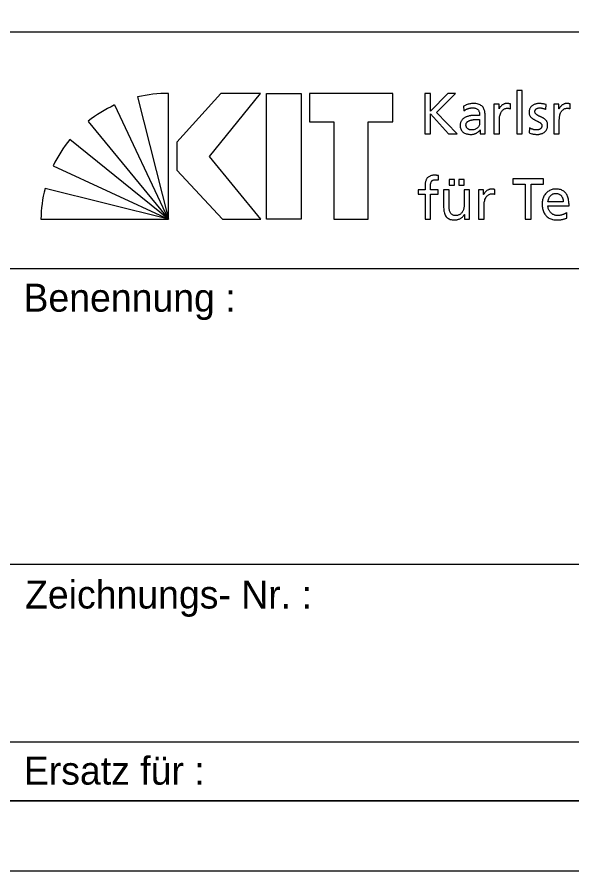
# Model space of a CAD drawing. Extents: x 0 to 119, y 0 to 84.
# Drawn here: x 101.13 to 109.07, y 0 to 12.21 of the extents above; entities that cross this region are included whole.
import ezdxf

# ---------------------------------------------------------------- set-up
doc = ezdxf.new("R2010")
doc.units = 0
doc.layers.add('90_Plankopf', color=7, linetype='Continuous')

msp = doc.modelspace()

# ---------------------------------------------------------------- linework, layer by layer
at = {"layer": '90_Plankopf'}
for p, q in [((82.224, 11.998), (117.8, 11.998)), ((82.224, 11.998), (117.8, 11.998)), ((103.296, 9.317), (103.296, 11.117)), ((106.962, 11.117), (106.962, 10.541)), ((102.855, 11.067), (103.296, 9.317)), ((103.296, 9.317), (102.527, 10.95)), ((107.516, 10.932), (107.52, 10.866)), ((108.185, 10.897), (108.185, 10.966)), ((108.691, 10.888), (108.698, 10.956)), ((109.042, 10.897), (109.042, 10.966)), ((107.824, 10.624), (107.824, 10.798)), ((102.149, 10.717), (103.296, 9.317)), ((107.746, 10.742), (107.746, 10.705)), ((108.459, 10.624), (108.455, 10.554)), ((106.962, 10.541), (107.044, 10.541)), ((107.301, 10.541), (107.422, 10.541)), ((103.296, 9.317), (101.887, 10.457)), ((101.648, 10.083), (103.296, 9.317)), ((107.155, 9.879), (107.158, 9.941)), ((103.296, 9.317), (101.532, 9.758)), ((107.965, 9.673), (107.965, 9.742)), ((108.941, 9.568), (108.723, 9.568)), ((108.723, 9.51), (109.024, 9.51)), ((108.992, 9.335), (108.992, 9.412)), ((101.473, 9.317), (103.296, 9.317)), ((101, 8.614), (117.8, 8.614)), ((101, 4.384), (117.8, 4.384)), ((101, 1.846), (117.8, 1.846)), ((117.8, 1), (82.224, 1)), ((84.56, 1), (117.8, 1)), ((84.56, 1), (117.8, 1))]:
    msp.add_line(p, q, dxfattribs=at)
for points in [[(0, 0), (118.8, 0), (118.8, 84), (0, 84)], [(5, 83), (117.8, 83), (117.8, 1), (5, 1)], [(104.613, 11.117), (104.047, 11.117), (103.415, 10.42), (103.415, 10.018), (104.068, 9.317), (104.617, 9.317), (103.884, 10.213)], [(105.194, 11.117), (105.194, 9.317), (104.7, 9.317), (104.7, 11.117)], [(105.312, 11.117), (105.312, 10.712), (105.66, 10.712), (105.66, 9.317), (106.154, 9.317), (106.154, 10.712), (106.502, 10.712), (106.502, 11.117)]]:
    msp.add_lwpolyline(points, close=True, dxfattribs=at)
for points in [[(107.422, 10.541), (107.129, 10.845), (107.4, 11.117), (107.29, 11.117), (107.044, 10.864), (107.044, 11.117), (106.962, 11.117)], [(108.276, 10.541), (108.354, 10.541), (108.354, 11.16), (108.276, 11.16), (108.276, 10.541)], [(108.024, 10.897), (108.023, 10.897), (108.023, 10.962), (107.95, 10.962), (107.95, 10.541), (108.028, 10.541), (108.028, 10.733)], [(108.881, 10.897), (108.88, 10.897), (108.88, 10.962), (108.807, 10.962), (108.807, 10.541), (108.885, 10.541), (108.885, 10.733)], [(107.044, 10.541), (107.044, 10.823), (107.301, 10.541)], [(107.753, 10.596), (107.754, 10.596), (107.754, 10.541), (107.827, 10.541)], [(108.398, 9.317), (108.481, 9.317), (108.481, 9.821), (108.66, 9.821), (108.66, 9.893), (108.219, 9.893), (108.219, 9.821), (108.398, 9.821), (108.398, 9.317)], [(106.965, 9.777), (106.965, 9.738), (106.866, 9.738), (106.866, 9.676), (106.965, 9.676), (106.965, 9.317), (107.042, 9.317), (107.042, 9.676), (107.154, 9.676), (107.154, 9.738), (107.042, 9.738), (107.042, 9.784)], [(107.311, 9.885), (107.311, 9.803), (107.388, 9.803), (107.388, 9.885), (107.311, 9.885)], [(107.446, 9.885), (107.446, 9.803), (107.524, 9.803), (107.524, 9.885), (107.446, 9.885)], [(107.308, 9.52), (107.308, 9.738), (107.231, 9.738), (107.231, 9.488)], [(107.603, 9.317), (107.603, 9.738), (107.525, 9.738), (107.525, 9.543)], [(107.804, 9.673), (107.803, 9.673), (107.803, 9.738), (107.73, 9.738), (107.73, 9.317), (107.808, 9.317), (107.808, 9.509)], [(107.526, 9.384), (107.528, 9.384), (107.528, 9.317), (107.603, 9.317)]]:
    msp.add_lwpolyline(points, dxfattribs=at)
for centre, start, end in [((103.29, 9.211), 89.8053, 103.1895), ((103.332, 9.224), 115.0126, 128.3968), ((103.363, 9.253), 140.7898, 154.174), ((103.378, 9.288), 165.7222, 179.1064)]:
    msp.add_arc(centre, 1.906, start, end, dxfattribs=at)
for points in [[(107.824, 10.798), (107.824, 10.836), (107.818, 10.868), (107.807, 10.894), (107.795, 10.92), (107.777, 10.939), (107.752, 10.952), (107.727, 10.965), (107.694, 10.972), (107.654, 10.972), (107.628, 10.972), (107.603, 10.968), (107.58, 10.961), (107.556, 10.954), (107.535, 10.944), (107.516, 10.932)], [(107.52, 10.866), (107.531, 10.875), (107.543, 10.883), (107.556, 10.889), (107.569, 10.896), (107.583, 10.901), (107.598, 10.904), (107.613, 10.908), (107.627, 10.909), (107.642, 10.909), (107.668, 10.909), (107.688, 10.905), (107.704, 10.897), (107.719, 10.889), (107.73, 10.877), (107.736, 10.86), (107.743, 10.844), (107.746, 10.824), (107.746, 10.799)], [(108.185, 10.966), (108.18, 10.967), (108.175, 10.968), (108.17, 10.969), (108.165, 10.97), (108.16, 10.971), (108.154, 10.971), (108.148, 10.972), (108.142, 10.972), (108.134, 10.972), (108.119, 10.972), (108.105, 10.969), (108.09, 10.962), (108.076, 10.956), (108.064, 10.947), (108.052, 10.936), (108.041, 10.925), (108.031, 10.912), (108.024, 10.897)], [(108.028, 10.733), (108.028, 10.768), (108.033, 10.799), (108.042, 10.824), (108.051, 10.85), (108.065, 10.87), (108.082, 10.883), (108.099, 10.897), (108.119, 10.904), (108.142, 10.904), (108.149, 10.904), (108.156, 10.904), (108.164, 10.903), (108.171, 10.902), (108.178, 10.9), (108.185, 10.897)], [(108.698, 10.956), (108.683, 10.96), (108.667, 10.964), (108.652, 10.967), (108.636, 10.97), (108.619, 10.972), (108.601, 10.972), (108.581, 10.972), (108.561, 10.969), (108.543, 10.964), (108.525, 10.959), (108.509, 10.951), (108.496, 10.94), (108.482, 10.929), (108.472, 10.916), (108.464, 10.9), (108.457, 10.883), (108.453, 10.864), (108.453, 10.842), (108.453, 10.826), (108.456, 10.811), (108.463, 10.799), (108.469, 10.787), (108.478, 10.776), (108.489, 10.767), (108.5, 10.758), (108.512, 10.75), (108.525, 10.743), (108.538, 10.736), (108.551, 10.729), (108.563, 10.723), (108.576, 10.717), (108.588, 10.711), (108.599, 10.704), (108.61, 10.698), (108.619, 10.691), (108.625, 10.683), (108.632, 10.675), (108.635, 10.665), (108.635, 10.654), (108.635, 10.643), (108.633, 10.633), (108.628, 10.626), (108.623, 10.618), (108.617, 10.612), (108.609, 10.607), (108.601, 10.602), (108.593, 10.599), (108.583, 10.597), (108.574, 10.595), (108.565, 10.594), (108.556, 10.594), (108.548, 10.594), (108.539, 10.595), (108.528, 10.597), (108.517, 10.599), (108.505, 10.603), (108.493, 10.607), (108.481, 10.612), (108.47, 10.617), (108.459, 10.624)], [(108.455, 10.554), (108.473, 10.545), (108.492, 10.539), (108.512, 10.536), (108.531, 10.532), (108.551, 10.531), (108.571, 10.531), (108.59, 10.531), (108.608, 10.534), (108.625, 10.539), (108.643, 10.544), (108.659, 10.552), (108.673, 10.563), (108.686, 10.574), (108.697, 10.588), (108.705, 10.604), (108.714, 10.621), (108.718, 10.64), (108.718, 10.662), (108.718, 10.682), (108.714, 10.698), (108.708, 10.711), (108.701, 10.724), (108.692, 10.736), (108.682, 10.745), (108.671, 10.754), (108.659, 10.762), (108.646, 10.769), (108.633, 10.776), (108.62, 10.782), (108.607, 10.787), (108.594, 10.793), (108.582, 10.799), (108.572, 10.805), (108.561, 10.812), (108.552, 10.819), (108.545, 10.827), (108.539, 10.836), (108.536, 10.846), (108.535, 10.858), (108.536, 10.87), (108.539, 10.879), (108.546, 10.887), (108.553, 10.894), (108.562, 10.9), (108.573, 10.904), (108.584, 10.908), (108.596, 10.909), (108.61, 10.909), (108.614, 10.909), (108.62, 10.909), (108.628, 10.908), (108.635, 10.906), (108.643, 10.905), (108.651, 10.903), (108.659, 10.901), (108.667, 10.898), (108.674, 10.896), (108.681, 10.893), (108.687, 10.891), (108.691, 10.888)], [(109.042, 10.966), (109.037, 10.967), (109.032, 10.968), (109.027, 10.969), (109.022, 10.97), (109.017, 10.971), (109.011, 10.971), (109.005, 10.972), (108.999, 10.972), (108.991, 10.972), (108.976, 10.972), (108.962, 10.969), (108.947, 10.962), (108.933, 10.956), (108.921, 10.947), (108.909, 10.936), (108.898, 10.925), (108.888, 10.912), (108.881, 10.897)], [(108.885, 10.733), (108.885, 10.768), (108.89, 10.799), (108.899, 10.824), (108.908, 10.85), (108.922, 10.87), (108.939, 10.883), (108.956, 10.897), (108.976, 10.904), (108.999, 10.904), (109.006, 10.904), (109.013, 10.904), (109.021, 10.903), (109.028, 10.902), (109.035, 10.9), (109.042, 10.897)], [(107.746, 10.799), (107.736, 10.8), (107.727, 10.8), (107.718, 10.801), (107.709, 10.801), (107.7, 10.801), (107.692, 10.801), (107.683, 10.801), (107.674, 10.801), (107.664, 10.801), (107.647, 10.801), (107.63, 10.8), (107.613, 10.797), (107.595, 10.794), (107.577, 10.789), (107.56, 10.783), (107.543, 10.776), (107.528, 10.768), (107.514, 10.757), (107.5, 10.746), (107.489, 10.733), (107.481, 10.718), (107.472, 10.702), (107.468, 10.684), (107.468, 10.662), (107.468, 10.632), (107.475, 10.607), (107.488, 10.588), (107.501, 10.568), (107.519, 10.554), (107.542, 10.545), (107.565, 10.536), (107.592, 10.531), (107.622, 10.531), (107.64, 10.531), (107.656, 10.534), (107.67, 10.538), (107.684, 10.542), (107.697, 10.547), (107.707, 10.554), (107.718, 10.56), (107.727, 10.567), (107.735, 10.575), (107.742, 10.582), (107.748, 10.589), (107.753, 10.596)], [(107.746, 10.705), (107.746, 10.684), (107.742, 10.665), (107.733, 10.648), (107.724, 10.631), (107.711, 10.618), (107.693, 10.609), (107.676, 10.599), (107.654, 10.594), (107.629, 10.594), (107.62, 10.594), (107.611, 10.596), (107.602, 10.598), (107.593, 10.601), (107.584, 10.606), (107.576, 10.611), (107.569, 10.617), (107.562, 10.625), (107.558, 10.633), (107.553, 10.641), (107.551, 10.651), (107.55, 10.662), (107.551, 10.677), (107.554, 10.69), (107.562, 10.699), (107.569, 10.709), (107.578, 10.717), (107.59, 10.723), (107.601, 10.729), (107.614, 10.733), (107.627, 10.736), (107.64, 10.739), (107.653, 10.741), (107.665, 10.742), (107.677, 10.743), (107.688, 10.743), (107.697, 10.743), (107.705, 10.743), (107.713, 10.743), (107.721, 10.743), (107.73, 10.742), (107.738, 10.742), (107.746, 10.742)], [(107.827, 10.541), (107.826, 10.545), (107.826, 10.551), (107.825, 10.557), (107.825, 10.564), (107.824, 10.573), (107.824, 10.584), (107.824, 10.595), (107.824, 10.608), (107.824, 10.624)], [(107.158, 9.941), (107.15, 9.942), (107.142, 9.944), (107.134, 9.945), (107.125, 9.946), (107.116, 9.946), (107.106, 9.946), (107.078, 9.946), (107.054, 9.942), (107.036, 9.934), (107.017, 9.926), (107.003, 9.915), (106.992, 9.9), (106.982, 9.885), (106.975, 9.867), (106.971, 9.847), (106.967, 9.826), (106.965, 9.803), (106.965, 9.777)], [(107.042, 9.784), (107.042, 9.798), (107.043, 9.811), (107.045, 9.823), (107.046, 9.835), (107.05, 9.846), (107.055, 9.855), (107.06, 9.864), (107.068, 9.871), (107.078, 9.876), (107.088, 9.881), (107.101, 9.883), (107.118, 9.883), (107.124, 9.883), (107.131, 9.883), (107.138, 9.882), (107.144, 9.881), (107.15, 9.88), (107.155, 9.879)], [(107.965, 9.742), (107.96, 9.743), (107.955, 9.744), (107.95, 9.745), (107.945, 9.746), (107.94, 9.747), (107.934, 9.747), (107.928, 9.748), (107.922, 9.748), (107.914, 9.748), (107.899, 9.748), (107.885, 9.745), (107.87, 9.738), (107.856, 9.732), (107.844, 9.723), (107.832, 9.712), (107.821, 9.701), (107.811, 9.688), (107.804, 9.673)], [(107.808, 9.509), (107.808, 9.544), (107.813, 9.575), (107.822, 9.6), (107.832, 9.626), (107.845, 9.646), (107.862, 9.659), (107.879, 9.673), (107.899, 9.68), (107.922, 9.68), (107.929, 9.681), (107.936, 9.68), (107.944, 9.679), (107.951, 9.678), (107.958, 9.676), (107.965, 9.673)], [(109.024, 9.51), (109.024, 9.544), (109.021, 9.576), (109.014, 9.605), (109.008, 9.634), (108.998, 9.659), (108.984, 9.68), (108.969, 9.701), (108.95, 9.718), (108.926, 9.73), (108.902, 9.742), (108.873, 9.748), (108.838, 9.748), (108.808, 9.748), (108.781, 9.743), (108.757, 9.732), (108.733, 9.722), (108.712, 9.707), (108.695, 9.688), (108.677, 9.669), (108.664, 9.647), (108.655, 9.621), (108.646, 9.595), (108.641, 9.567), (108.641, 9.535), (108.641, 9.501), (108.645, 9.47), (108.654, 9.442), (108.662, 9.414), (108.676, 9.39), (108.694, 9.37), (108.712, 9.35), (108.734, 9.334), (108.762, 9.324), (108.789, 9.313), (108.821, 9.308), (108.859, 9.307), (108.882, 9.308), (108.901, 9.309), (108.917, 9.312), (108.933, 9.315), (108.947, 9.319), (108.959, 9.323), (108.971, 9.327), (108.982, 9.331), (108.992, 9.335)], [(108.723, 9.568), (108.725, 9.582), (108.728, 9.596), (108.733, 9.609), (108.738, 9.623), (108.744, 9.636), (108.754, 9.647), (108.762, 9.659), (108.774, 9.668), (108.787, 9.675), (108.801, 9.682), (108.817, 9.685), (108.836, 9.685), (108.853, 9.685), (108.868, 9.682), (108.881, 9.676), (108.894, 9.67), (108.905, 9.662), (108.914, 9.651), (108.923, 9.64), (108.93, 9.628), (108.934, 9.614), (108.939, 9.6), (108.941, 9.584), (108.941, 9.568)], [(107.525, 9.543), (107.525, 9.518), (107.523, 9.494), (107.518, 9.473), (107.513, 9.452), (107.505, 9.434), (107.495, 9.418), (107.484, 9.403), (107.471, 9.391), (107.455, 9.383), (107.439, 9.374), (107.419, 9.37), (107.397, 9.37), (107.375, 9.371), (107.357, 9.378), (107.344, 9.389), (107.331, 9.4), (107.322, 9.417), (107.316, 9.439), (107.311, 9.46), (107.308, 9.488), (107.308, 9.52)], [(107.231, 9.488), (107.231, 9.45), (107.236, 9.418), (107.247, 9.391), (107.259, 9.364), (107.276, 9.343), (107.299, 9.329), (107.322, 9.315), (107.352, 9.308), (107.388, 9.307), (107.408, 9.308), (107.427, 9.311), (107.445, 9.317), (107.463, 9.323), (107.479, 9.332), (107.493, 9.343), (107.507, 9.354), (107.518, 9.368), (107.526, 9.384)], [(108.992, 9.412), (108.987, 9.408), (108.98, 9.404), (108.97, 9.399), (108.961, 9.394), (108.951, 9.39), (108.939, 9.385), (108.927, 9.381), (108.914, 9.377), (108.901, 9.374), (108.888, 9.372), (108.875, 9.37), (108.862, 9.37), (108.843, 9.37), (108.826, 9.374), (108.809, 9.38), (108.793, 9.387), (108.778, 9.397), (108.765, 9.409), (108.752, 9.421), (108.742, 9.436), (108.735, 9.453), (108.727, 9.471), (108.723, 9.49), (108.723, 9.51)]]:
    msp.add_open_spline(points, degree=3, dxfattribs=at)

# ---------------------------------------------------------------- texts
for s, p in [('Benennung :', (101.223, 7.996)), ('Zeichnungs- Nr. :', (101.245, 3.752)), ('Ersatz für :', (101.228, 1.234))]:
    msp.add_text(s, height=0.4, dxfattribs=at).set_placement(p)

doc.saveas('drawing.dxf')
